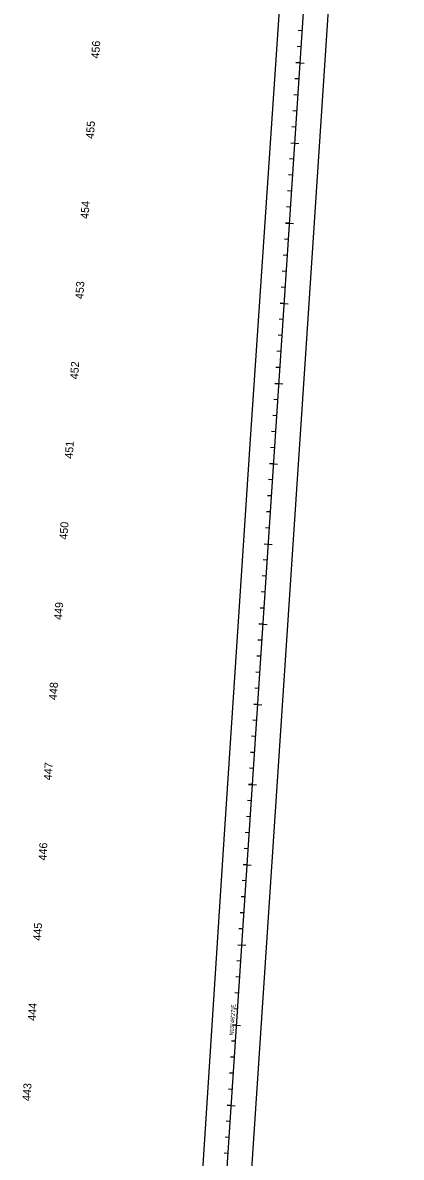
# Model space of a CAD drawing. Extents: x 1699999 to 1705087, y 475568 to 482652.
# Drawn here: x 1702975 to 1703446, y 479819 to 481231 of the extents above; entities that cross this region are included whole.
import ezdxf

# ---------------------------------------------------------------- set-up
doc = ezdxf.new("R2010")
doc.units = 0
for name, color, linetype in [('Default', 7, 'Continuous'), ('DES - DTM - Ground', 7, 'Continuous'), ('DES - DTM - Points - High', 7, 'Continuous'), ('DESIGN - TYPICAL - Guardrail', 7, 'Continuous'), ('TC_Aggregate', 7, 'Continuous')]:
    doc.layers.add(name, color=color, linetype=linetype)

msp = doc.modelspace()

# ---------------------------------------------------------------- linework, layer by layer
at = {"layer": 'Default'}
msp.add_line((1703065.1, 477316.2), (1703415.3, 482625.1), dxfattribs=at)
at = {"layer": 'DES - DTM - Ground'}
msp.add_line((1703065.1, 477316.2), (1703415.3, 482625.1), dxfattribs=at)
for points in [[(1703182.2, 479545.9), (1703224.8, 480202.3), (1703257.7, 480700.5), (1703309.7, 481474.6), (1703350.7, 482106.4), (1703384.7, 482627.1)], [(1703259.7, 479798.3), (1703310.9, 480575.7), (1703327.5, 480825.1), (1703410, 482072.1), (1703446.2, 482623)]]:
    msp.add_lwpolyline(points, dxfattribs=at)
at = {"layer": 'DES - DTM - Points - High'}
for p, q in [((1703322.6, 481221), (1703317.7, 481221.3)), ((1703321.3, 481201), (1703316.3, 481201.3)), ((1703315, 481181.4), (1703325, 481180.7)), ((1703318.7, 481161.1), (1703313.7, 481161.4)), ((1703317.4, 481141.1), (1703312.4, 481141.5)), ((1703316, 481121.2), (1703311.1, 481121.5)), ((1703314.7, 481101.2), (1703309.8, 481101.5)), ((1703308.4, 481081.6), (1703318.4, 481080.9)), ((1703312.1, 481061.3), (1703307.1, 481061.6)), ((1703310.8, 481041.4), (1703305.8, 481041.7)), ((1703309.5, 481021.4), (1703304.5, 481021.7)), ((1703308.1, 481001.4), (1703303.2, 481001.8)), ((1703301.8, 480981.8), (1703311.8, 480981.2)), ((1703305.5, 480961.5), (1703300.5, 480961.9)), ((1703304.2, 480941.6), (1703299.2, 480941.9)), ((1703302.9, 480921.6), (1703297.9, 480921.9)), ((1703301.6, 480901.7), (1703296.6, 480902)), ((1703295.3, 480882), (1703305.2, 480881.4)), ((1703298.9, 480861.7), (1703294, 480862.1)), ((1703297.6, 480841.8), (1703292.6, 480842.1)), ((1703296.3, 480821.8), (1703291.3, 480822.2)), ((1703295, 480801.9), (1703290, 480802.2)), ((1703288.7, 480782.2), (1703298.7, 480781.6)), ((1703292.4, 480762), (1703287.4, 480762.3)), ((1703291, 480742), (1703286.1, 480742.3)), ((1703289.7, 480722), (1703284.7, 480722.4)), ((1703288.4, 480702.1), (1703283.4, 480702.4)), ((1703282.1, 480682.5), (1703292.1, 480681.8)), ((1703285.8, 480662.2), (1703280.8, 480662.5)), ((1703284.5, 480642.2), (1703279.5, 480642.5)), ((1703283.1, 480622.3), (1703278.2, 480622.6)), ((1703281.8, 480602.3), (1703276.9, 480602.6)), ((1703275.5, 480582.7), (1703285.5, 480582)), ((1703279.2, 480562.4), (1703274.2, 480562.7)), ((1703277.9, 480542.4), (1703272.9, 480542.8)), ((1703276.6, 480522.5), (1703271.6, 480522.8)), ((1703275.2, 480502.5), (1703270.3, 480502.8)), ((1703268.9, 480482.9), (1703278.9, 480482.2)), ((1703272.6, 480462.6), (1703267.6, 480462.9)), ((1703271.3, 480442.7), (1703266.3, 480443)), ((1703270, 480422.7), (1703265, 480423)), ((1703268.7, 480402.7), (1703263.7, 480403.1)), ((1703262.4, 480383.1), (1703272.3, 480382.5)), ((1703266, 480362.8), (1703261.1, 480363.2)), ((1703264.7, 480342.9), (1703259.7, 480343.2)), ((1703263.4, 480322.9), (1703258.4, 480323.2)), ((1703262.1, 480303), (1703257.1, 480303.3)), ((1703255.8, 480283.3), (1703265.7, 480282.7)), ((1703259.4, 480263), (1703254.5, 480263.4)), ((1703258.1, 480243.1), (1703253.2, 480243.4)), ((1703256.8, 480223.1), (1703251.8, 480223.5)), ((1703255.5, 480203.2), (1703250.5, 480203.5)), ((1703249.2, 480183.5), (1703259.2, 480182.9)), ((1703252.9, 480163.3), (1703247.9, 480163.6)), ((1703251.5, 480143.3), (1703246.6, 480143.6)), ((1703250.2, 480123.3), (1703245.3, 480123.7)), ((1703248.9, 480103.4), (1703243.9, 480103.7)), ((1703242.6, 480083.8), (1703252.6, 480083.1)), ((1703246.3, 480063.5), (1703241.3, 480063.8)), ((1703245, 480043.5), (1703240, 480043.8)), ((1703243.6, 480023.6), (1703238.7, 480023.9)), ((1703242.3, 480003.6), (1703237.4, 480003.9)), ((1703236, 479984), (1703246, 479983.3)), ((1703239.7, 479963.7), (1703234.7, 479964)), ((1703238.4, 479943.7), (1703233.4, 479944.1)), ((1703237.1, 479923.8), (1703232.1, 479924.1)), ((1703235.7, 479903.8), (1703230.8, 479904.2)), ((1703229.4, 479884.2), (1703239.4, 479883.5)), ((1703233.1, 479863.9), (1703228.1, 479864.2)), ((1703231.8, 479844), (1703226.8, 479844.3)), ((1703230.5, 479824), (1703225.5, 479824.3))]:
    msp.add_line(p, q, dxfattribs=at)
at = {"layer": 'DESIGN - TYPICAL - Guardrail'}
for p, q in [((1703320, 481181), (1703315, 481181.4)), ((1703308.4, 481081.6), (1703318.4, 481080.9)), ((1703306.8, 480981.5), (1703301.9, 480981.8)), ((1703300.3, 480881.7), (1703295.3, 480882)), ((1703293.7, 480781.9), (1703288.7, 480782.2)), ((1703287.1, 480682.1), (1703282.1, 480682.5)), ((1703275.5, 480582.7), (1703285.5, 480582)), ((1703273.9, 480482.6), (1703269, 480482.9)), ((1703267.3, 480382.8), (1703262.4, 480383.1)), ((1703260.8, 480283), (1703255.8, 480283.3)), ((1703254.2, 480183.2), (1703249.2, 480183.5)), ((1703242.6, 480083.8), (1703252.6, 480083.1)), ((1703241, 479983.6), (1703236, 479984)), ((1703234.4, 479883.9), (1703229.5, 479884.2))]:
    msp.add_line(p, q, dxfattribs=at)

# ---------------------------------------------------------------- texts
at = {"layer": 'DES - DTM - Points - High'}
for s, p in [('456', (1703069.8, 481186.2)), ('455', (1703063.2, 481086.4)), ('454', (1703056.6, 480986.7)), ('453', (1703050, 480886.9)), ('452', (1703043.5, 480787.2)), ('451', (1703036.9, 480688.3)), ('450', (1703030.3, 480587.6)), ('449', (1703023.7, 480487.7)), ('448', (1703017.1, 480388)), ('447', (1703010.6, 480288.2)), ('446', (1703004, 480188.4)), ('445', (1702997.4, 480088.6)), ('444', (1702990.8, 479988.9)), ('443', (1702984.2, 479889.1))]:
    msp.add_text(s, height=9.96, rotation=86.2259, dxfattribs=at).set_placement(p)
at = {"layer": 'DESIGN - TYPICAL - Guardrail'}
for s, p in [('455', (1703063.2, 481086.4)), ('450', (1703030.3, 480587.6)), ('445', (1702997.4, 480088.6))]:
    msp.add_text(s, height=9.96, rotation=86.2259, dxfattribs=at).set_placement(p)
at = {"layer": 'TC_Aggregate'}
msp.add_text('N03°46\'27"E', height=4.98, rotation=86.2259, dxfattribs=at).set_placement((1703237.2, 479970.8))

doc.saveas('drawing.dxf')
